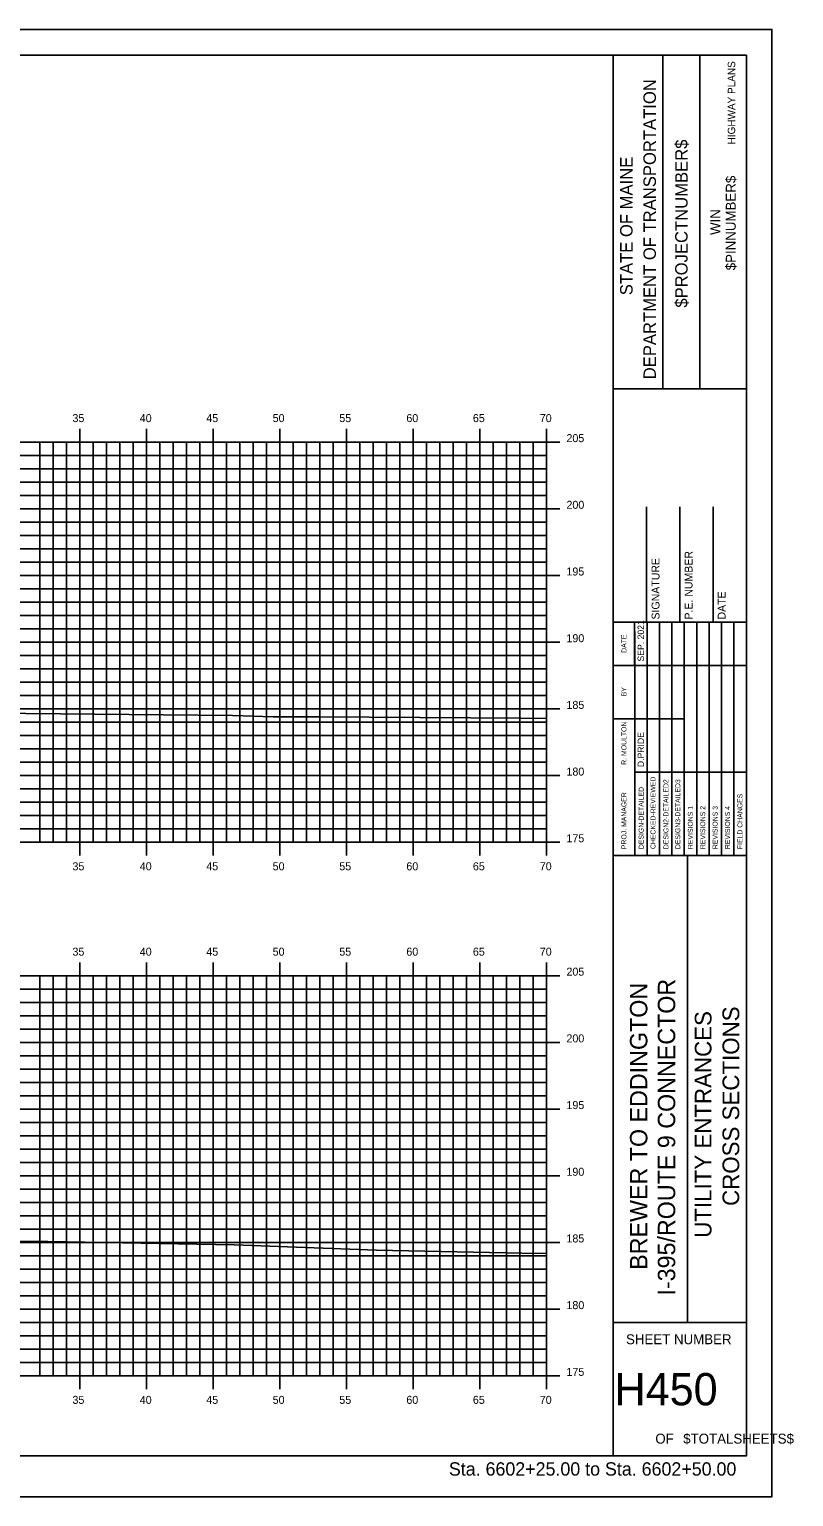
# Model space of a CAD drawing. Extents: x 1724183 to 1724355, y 459560 to 459670.
# Drawn here: x 1724297.4 to 1724354.8, y 459559.6 to 459669.6 of the extents above; entities that cross this region are included whole.
import ezdxf

# ---------------------------------------------------------------- set-up
doc = ezdxf.new("R2010")
doc.units = 0
for name, color, linetype in [('BORDER', 7, 'Continuous'), ('H_V ANNOTATION', 7, 'Continuous'), ('HIGHWAY_TITLE', 7, 'Continuous'), ('MAJOR', 7, 'Continuous'), ('MINOR', 7, 'Continuous'), ('PLOT BOUNDARY', 7, 'Continuous'), ('S_Roadway_Centerline', 7, 'Continuous')]:
    doc.layers.add(name, color=color, linetype=linetype)

msp = doc.modelspace()

# ---------------------------------------------------------------- linework, layer by layer
at = {"layer": 'BORDER'}
for p, q in [((1724341.23, 459562.61), (1724341.23, 459667.61)), ((1724344.96, 459642.61), (1724344.96, 459667.61)), ((1724347.75, 459642.61), (1724347.75, 459667.61)), ((1724341.23, 459642.61), (1724351.23, 459642.61)), ((1724343.73, 459625.12), (1724343.73, 459633.76)), ((1724346.23, 459625.12), (1724346.23, 459633.76)), ((1724348.73, 459625.12), (1724348.73, 459633.76)), ((1724341.23, 459625.12), (1724351.23, 459625.12)), ((1724341.23, 459607.62), (1724351.23, 459607.62)), ((1724346.82, 459572.62), (1724346.82, 459607.62)), ((1724341.23, 459572.62), (1724351.23, 459572.62))]:
    msp.add_line(p, q, dxfattribs=at)
msp.add_lwpolyline([(1724191.23, 459562.61), (1724351.23, 459562.61), (1724351.23, 459667.61), (1724191.23, 459667.61)], close=True, dxfattribs=at)
for points in [[(1724342.84, 459621.87), (1724342.84, 459625.12)], [(1724343.78, 459607.62), (1724343.78, 459625.12)], [(1724344.71, 459625.12), (1724344.71, 459607.62)], [(1724345.64, 459607.62), (1724345.64, 459625.12)], [(1724346.57, 459607.62), (1724346.57, 459625.12)], [(1724347.5, 459607.62), (1724347.5, 459625.12)], [(1724348.44, 459607.62), (1724348.44, 459625.12)], [(1724349.37, 459607.62), (1724349.37, 459625.12)], [(1724350.3, 459607.62), (1724350.3, 459625.12)], [(1724342.85, 459607.62), (1724342.85, 459624.41)], [(1724341.23, 459621.87), (1724351.23, 459621.87)], [(1724341.23, 459617.87), (1724342.85, 459617.87)], [(1724342.84, 459617.87), (1724346.57, 459617.87)], [(1724342.84, 459613.87), (1724351.23, 459613.87)]]:
    msp.add_lwpolyline(points, dxfattribs=at)
at = {"layer": 'MAJOR'}
for p, q in [((1724301.23, 459639.61), (1724301.23, 459638.61)), ((1724306.23, 459639.61), (1724306.23, 459638.61)), ((1724311.23, 459639.61), (1724311.23, 459638.61)), ((1724316.23, 459639.61), (1724316.23, 459638.61)), ((1724321.23, 459639.61), (1724321.23, 459638.61)), ((1724326.23, 459639.61), (1724326.23, 459638.61)), ((1724331.23, 459639.61), (1724331.23, 459638.61)), ((1724336.23, 459639.61), (1724336.23, 459638.61)), ((1724196.23, 459638.61), (1724336.23, 459638.61)), ((1724196.23, 459638.61), (1724336.23, 459638.61)), ((1724301.23, 459608.61), (1724301.23, 459638.61)), ((1724306.23, 459608.61), (1724306.23, 459638.61)), ((1724311.23, 459608.61), (1724311.23, 459638.61)), ((1724316.23, 459608.61), (1724316.23, 459638.61)), ((1724321.23, 459608.61), (1724321.23, 459638.61)), ((1724326.23, 459608.61), (1724326.23, 459638.61)), ((1724331.23, 459608.61), (1724331.23, 459638.61)), ((1724337.23, 459638.61), (1724335.23, 459638.61)), ((1724336.23, 459608.61), (1724336.23, 459638.61)), ((1724336.23, 459608.61), (1724336.23, 459638.61)), ((1724196.23, 459633.61), (1724336.23, 459633.61)), ((1724337.23, 459633.61), (1724335.23, 459633.61)), ((1724196.23, 459628.61), (1724336.23, 459628.61)), ((1724337.23, 459628.61), (1724335.23, 459628.61)), ((1724196.23, 459623.61), (1724336.23, 459623.61)), ((1724337.23, 459623.61), (1724335.23, 459623.61)), ((1724196.23, 459618.61), (1724336.23, 459618.61)), ((1724337.23, 459618.61), (1724335.23, 459618.61)), ((1724196.23, 459613.61), (1724336.23, 459613.61)), ((1724337.23, 459613.61), (1724335.23, 459613.61)), ((1724196.23, 459608.61), (1724336.23, 459608.61)), ((1724196.23, 459608.61), (1724336.23, 459608.61)), ((1724301.23, 459607.61), (1724301.23, 459608.61)), ((1724306.23, 459607.61), (1724306.23, 459608.61)), ((1724311.23, 459607.61), (1724311.23, 459608.61)), ((1724316.23, 459607.61), (1724316.23, 459608.61)), ((1724321.23, 459607.61), (1724321.23, 459608.61)), ((1724326.23, 459607.61), (1724326.23, 459608.61)), ((1724331.23, 459607.61), (1724331.23, 459608.61)), ((1724337.23, 459608.61), (1724335.23, 459608.61)), ((1724336.23, 459607.61), (1724336.23, 459608.61)), ((1724301.23, 459599.61), (1724301.23, 459598.61)), ((1724306.23, 459599.61), (1724306.23, 459598.61)), ((1724311.23, 459599.61), (1724311.23, 459598.61)), ((1724316.23, 459599.61), (1724316.23, 459598.61)), ((1724321.23, 459599.61), (1724321.23, 459598.61)), ((1724326.23, 459599.61), (1724326.23, 459598.61)), ((1724331.23, 459599.61), (1724331.23, 459598.61)), ((1724336.23, 459599.61), (1724336.23, 459598.61)), ((1724196.23, 459598.61), (1724336.23, 459598.61)), ((1724196.23, 459598.61), (1724336.23, 459598.61)), ((1724301.23, 459568.61), (1724301.23, 459598.61)), ((1724306.23, 459568.61), (1724306.23, 459598.61)), ((1724311.23, 459568.61), (1724311.23, 459598.61)), ((1724316.23, 459568.61), (1724316.23, 459598.61)), ((1724321.23, 459568.61), (1724321.23, 459598.61)), ((1724326.23, 459568.61), (1724326.23, 459598.61)), ((1724331.23, 459568.61), (1724331.23, 459598.61)), ((1724337.23, 459598.61), (1724335.23, 459598.61)), ((1724336.23, 459568.61), (1724336.23, 459598.61)), ((1724336.23, 459568.61), (1724336.23, 459598.61)), ((1724196.23, 459593.61), (1724336.23, 459593.61)), ((1724337.23, 459593.61), (1724335.23, 459593.61)), ((1724196.23, 459588.61), (1724336.23, 459588.61)), ((1724337.23, 459588.61), (1724335.23, 459588.61)), ((1724196.23, 459583.61), (1724336.23, 459583.61)), ((1724337.23, 459583.61), (1724335.23, 459583.61)), ((1724196.23, 459578.61), (1724336.23, 459578.61)), ((1724337.23, 459578.61), (1724335.23, 459578.61)), ((1724196.23, 459573.61), (1724336.23, 459573.61)), ((1724337.23, 459573.61), (1724335.23, 459573.61)), ((1724196.23, 459568.61), (1724336.23, 459568.61)), ((1724196.23, 459568.61), (1724336.23, 459568.61)), ((1724301.23, 459567.61), (1724301.23, 459568.61)), ((1724306.23, 459567.61), (1724306.23, 459568.61)), ((1724311.23, 459567.61), (1724311.23, 459568.61)), ((1724316.23, 459567.61), (1724316.23, 459568.61)), ((1724321.23, 459567.61), (1724321.23, 459568.61)), ((1724326.23, 459567.61), (1724326.23, 459568.61)), ((1724331.23, 459567.61), (1724331.23, 459568.61)), ((1724337.23, 459568.61), (1724335.23, 459568.61)), ((1724336.23, 459567.61), (1724336.23, 459568.61))]:
    msp.add_line(p, q, dxfattribs=at)
at = {"layer": 'MINOR'}
for p, q in [((1724298.23, 459608.61), (1724298.23, 459638.61)), ((1724299.23, 459608.61), (1724299.23, 459638.61)), ((1724300.23, 459608.61), (1724300.23, 459638.61)), ((1724302.23, 459608.61), (1724302.23, 459638.61)), ((1724303.23, 459608.61), (1724303.23, 459638.61)), ((1724304.23, 459608.61), (1724304.23, 459638.61)), ((1724305.23, 459608.61), (1724305.23, 459638.61)), ((1724307.23, 459608.61), (1724307.23, 459638.61)), ((1724308.23, 459608.61), (1724308.23, 459638.61)), ((1724309.23, 459608.61), (1724309.23, 459638.61)), ((1724310.23, 459608.61), (1724310.23, 459638.61)), ((1724312.23, 459608.61), (1724312.23, 459638.61)), ((1724313.23, 459608.61), (1724313.23, 459638.61)), ((1724314.23, 459608.61), (1724314.23, 459638.61)), ((1724315.23, 459608.61), (1724315.23, 459638.61)), ((1724317.23, 459608.61), (1724317.23, 459638.61)), ((1724318.23, 459608.61), (1724318.23, 459638.61)), ((1724319.23, 459608.61), (1724319.23, 459638.61)), ((1724320.23, 459608.61), (1724320.23, 459638.61)), ((1724322.23, 459608.61), (1724322.23, 459638.61)), ((1724323.23, 459608.61), (1724323.23, 459638.61)), ((1724324.23, 459608.61), (1724324.23, 459638.61)), ((1724325.23, 459608.61), (1724325.23, 459638.61)), ((1724327.23, 459608.61), (1724327.23, 459638.61)), ((1724328.23, 459608.61), (1724328.23, 459638.61)), ((1724329.23, 459608.61), (1724329.23, 459638.61)), ((1724330.23, 459608.61), (1724330.23, 459638.61)), ((1724332.23, 459608.61), (1724332.23, 459638.61)), ((1724333.23, 459608.61), (1724333.23, 459638.61)), ((1724334.23, 459608.61), (1724334.23, 459638.61)), ((1724335.23, 459608.61), (1724335.23, 459638.61)), ((1724196.23, 459637.61), (1724336.23, 459637.61)), ((1724336.23, 459637.61), (1724335.23, 459637.61)), ((1724196.23, 459636.61), (1724336.23, 459636.61)), ((1724336.23, 459636.61), (1724335.23, 459636.61)), ((1724196.23, 459635.61), (1724336.23, 459635.61)), ((1724336.23, 459635.61), (1724335.23, 459635.61)), ((1724196.23, 459634.61), (1724336.23, 459634.61)), ((1724336.23, 459634.61), (1724335.23, 459634.61)), ((1724196.23, 459632.61), (1724336.23, 459632.61)), ((1724336.23, 459632.61), (1724335.23, 459632.61)), ((1724196.23, 459631.61), (1724336.23, 459631.61)), ((1724196.23, 459630.61), (1724336.23, 459630.61)), ((1724336.23, 459631.61), (1724335.23, 459631.61)), ((1724336.23, 459630.61), (1724335.23, 459630.61)), ((1724196.23, 459629.61), (1724336.23, 459629.61)), ((1724336.23, 459629.61), (1724335.23, 459629.61)), ((1724196.23, 459627.61), (1724336.23, 459627.61)), ((1724336.23, 459627.61), (1724335.23, 459627.61)), ((1724196.23, 459626.61), (1724336.23, 459626.61)), ((1724336.23, 459626.61), (1724335.23, 459626.61)), ((1724196.23, 459625.61), (1724336.23, 459625.61)), ((1724336.23, 459625.61), (1724335.23, 459625.61)), ((1724196.23, 459624.61), (1724336.23, 459624.61)), ((1724336.23, 459624.61), (1724335.23, 459624.61)), ((1724196.23, 459622.61), (1724336.23, 459622.61)), ((1724336.23, 459622.61), (1724335.23, 459622.61)), ((1724196.23, 459621.61), (1724336.23, 459621.61)), ((1724336.23, 459621.61), (1724335.23, 459621.61)), ((1724196.23, 459620.61), (1724336.23, 459620.61)), ((1724196.23, 459619.61), (1724336.23, 459619.61)), ((1724336.23, 459620.61), (1724335.23, 459620.61)), ((1724336.23, 459619.61), (1724335.23, 459619.61)), ((1724196.23, 459617.61), (1724336.23, 459617.61)), ((1724336.23, 459617.61), (1724335.23, 459617.61)), ((1724196.23, 459616.61), (1724336.23, 459616.61)), ((1724336.23, 459616.61), (1724335.23, 459616.61)), ((1724196.23, 459615.61), (1724336.23, 459615.61)), ((1724336.23, 459615.61), (1724335.23, 459615.61)), ((1724196.23, 459614.61), (1724336.23, 459614.61)), ((1724336.23, 459614.61), (1724335.23, 459614.61)), ((1724196.23, 459612.61), (1724336.23, 459612.61)), ((1724336.23, 459612.61), (1724335.23, 459612.61)), ((1724196.23, 459611.61), (1724336.23, 459611.61)), ((1724336.23, 459611.61), (1724335.23, 459611.61)), ((1724196.23, 459610.61), (1724336.23, 459610.61)), ((1724336.23, 459610.61), (1724335.23, 459610.61)), ((1724196.23, 459609.61), (1724336.23, 459609.61)), ((1724336.23, 459609.61), (1724335.23, 459609.61)), ((1724196.23, 459597.61), (1724336.23, 459597.61)), ((1724298.23, 459568.61), (1724298.23, 459598.61)), ((1724299.23, 459568.61), (1724299.23, 459598.61)), ((1724300.23, 459568.61), (1724300.23, 459598.61)), ((1724302.23, 459568.61), (1724302.23, 459598.61)), ((1724303.23, 459568.61), (1724303.23, 459598.61)), ((1724304.23, 459568.61), (1724304.23, 459598.61)), ((1724305.23, 459568.61), (1724305.23, 459598.61)), ((1724307.23, 459568.61), (1724307.23, 459598.61)), ((1724308.23, 459568.61), (1724308.23, 459598.61)), ((1724309.23, 459568.61), (1724309.23, 459598.61)), ((1724310.23, 459568.61), (1724310.23, 459598.61)), ((1724312.23, 459568.61), (1724312.23, 459598.61)), ((1724313.23, 459568.61), (1724313.23, 459598.61)), ((1724314.23, 459568.61), (1724314.23, 459598.61)), ((1724315.23, 459568.61), (1724315.23, 459598.61)), ((1724317.23, 459568.61), (1724317.23, 459598.61)), ((1724318.23, 459568.61), (1724318.23, 459598.61)), ((1724319.23, 459568.61), (1724319.23, 459598.61)), ((1724320.23, 459568.61), (1724320.23, 459598.61)), ((1724322.23, 459568.61), (1724322.23, 459598.61)), ((1724323.23, 459568.61), (1724323.23, 459598.61)), ((1724324.23, 459568.61), (1724324.23, 459598.61)), ((1724325.23, 459568.61), (1724325.23, 459598.61)), ((1724327.23, 459568.61), (1724327.23, 459598.61)), ((1724328.23, 459568.61), (1724328.23, 459598.61)), ((1724329.23, 459568.61), (1724329.23, 459598.61)), ((1724330.23, 459568.61), (1724330.23, 459598.61)), ((1724332.23, 459568.61), (1724332.23, 459598.61)), ((1724333.23, 459568.61), (1724333.23, 459598.61)), ((1724334.23, 459568.61), (1724334.23, 459598.61)), ((1724335.23, 459568.61), (1724335.23, 459598.61)), ((1724336.23, 459597.61), (1724335.23, 459597.61)), ((1724196.23, 459596.61), (1724336.23, 459596.61)), ((1724336.23, 459596.61), (1724335.23, 459596.61)), ((1724196.23, 459595.61), (1724336.23, 459595.61)), ((1724336.23, 459595.61), (1724335.23, 459595.61)), ((1724196.23, 459594.61), (1724336.23, 459594.61)), ((1724336.23, 459594.61), (1724335.23, 459594.61)), ((1724196.23, 459592.61), (1724336.23, 459592.61)), ((1724336.23, 459592.61), (1724335.23, 459592.61)), ((1724196.23, 459591.61), (1724336.23, 459591.61)), ((1724336.23, 459591.61), (1724335.23, 459591.61)), ((1724196.23, 459590.61), (1724336.23, 459590.61)), ((1724336.23, 459590.61), (1724335.23, 459590.61)), ((1724196.23, 459589.61), (1724336.23, 459589.61)), ((1724336.23, 459589.61), (1724335.23, 459589.61)), ((1724196.23, 459587.61), (1724336.23, 459587.61)), ((1724196.23, 459586.61), (1724336.23, 459586.61)), ((1724336.23, 459587.61), (1724335.23, 459587.61)), ((1724336.23, 459586.61), (1724335.23, 459586.61)), ((1724196.23, 459585.61), (1724336.23, 459585.61)), ((1724336.23, 459585.61), (1724335.23, 459585.61)), ((1724196.23, 459584.61), (1724336.23, 459584.61)), ((1724336.23, 459584.61), (1724335.23, 459584.61)), ((1724196.23, 459582.61), (1724336.23, 459582.61)), ((1724336.23, 459582.61), (1724335.23, 459582.61)), ((1724196.23, 459581.61), (1724336.23, 459581.61)), ((1724336.23, 459581.61), (1724335.23, 459581.61)), ((1724196.23, 459580.61), (1724336.23, 459580.61)), ((1724336.23, 459580.61), (1724335.23, 459580.61)), ((1724196.23, 459579.61), (1724336.23, 459579.61)), ((1724336.23, 459579.61), (1724335.23, 459579.61)), ((1724196.23, 459577.61), (1724336.23, 459577.61)), ((1724336.23, 459577.61), (1724335.23, 459577.61)), ((1724196.23, 459576.61), (1724336.23, 459576.61)), ((1724196.23, 459575.61), (1724336.23, 459575.61)), ((1724336.23, 459576.61), (1724335.23, 459576.61)), ((1724336.23, 459575.61), (1724335.23, 459575.61)), ((1724196.23, 459574.61), (1724336.23, 459574.61)), ((1724336.23, 459574.61), (1724335.23, 459574.61)), ((1724196.23, 459572.61), (1724336.23, 459572.61)), ((1724336.23, 459572.61), (1724335.23, 459572.61)), ((1724196.23, 459571.61), (1724336.23, 459571.61)), ((1724336.23, 459571.61), (1724335.23, 459571.61)), ((1724196.23, 459570.61), (1724336.23, 459570.61)), ((1724336.23, 459570.61), (1724335.23, 459570.61)), ((1724196.23, 459569.61), (1724336.23, 459569.61)), ((1724336.23, 459569.61), (1724335.23, 459569.61))]:
    msp.add_line(p, q, dxfattribs=at)
at = {"layer": 'PLOT BOUNDARY'}
msp.add_lwpolyline([(1724183.14, 459559.55), (1724353.14, 459559.55), (1724353.14, 459669.55), (1724183.14, 459669.55)], close=True, dxfattribs=at)
at = {"layer": 'S_Roadway_Centerline'}
for points in [[(1724196.23, 459621.01), (1724202.87, 459620.97), (1724210.73, 459620.93), (1724221.32, 459620.44), (1724223.87, 459620.3), (1724226.15, 459620.21), (1724235.09, 459620), (1724244.6, 459619.56), (1724248.06, 459619.5), (1724258.68, 459619.37), (1724270.2, 459618.67), (1724270.63, 459618.66), (1724271.14, 459618.64), (1724291.82, 459618.31), (1724294.57, 459618.28), (1724312.67, 459618.11), (1724315.73, 459618.02), (1724319.16, 459618.01), (1724334.32, 459617.92), (1724336.23, 459617.88)], [(1724196.23, 459582.21), (1724199.86, 459582.21), (1724204.03, 459581.98), (1724224.07, 459580.72), (1724224.93, 459580.68), (1724225.67, 459580.68), (1724240.81, 459580.73), (1724247.35, 459580.74), (1724247.69, 459580.74), (1724248.09, 459580.7), (1724259.98, 459579.47), (1724268.97, 459579.48), (1724274.27, 459579.41), (1724283.45, 459579.01), (1724291.81, 459578.76), (1724298.81, 459578.69), (1724312.8, 459578.43), (1724323.48, 459578.03), (1724334.38, 459577.81), (1724336.23, 459577.79)]]:
    msp.add_lwpolyline(points, dxfattribs=at)

# ---------------------------------------------------------------- texts
at = {"layer": 'BORDER'}
for s, height, p in [('DEPARTMENT OF TRANSPORTATION', 0.9318, (1724344.44, 459643.32)), ('$PROJECTNUMBER$', 0.9318, (1724346.82, 459648.69)), ('STATE OF MAINE', 0.9318, (1724342.69, 459649.62)), ('$PINNUMBER$', 0.7453, (1724350.43, 459651.49)), ('WIN', 0.745, (1724349.27, 459654.14)), ('SIGNATURE', 0.591, (1724344.71, 459625.31)), ('P.E. NUMBER', 0.5906, (1724347.19, 459625.31)), ('DATE', 0.591, (1724349.67, 459625.31)), ('SEP. 2021', 0.485, (1724343.55, 459622.16)), ('DATE', 0.371, (1724342.23, 459622.82)), ('BY', 0.371, (1724342.23, 459619.55)), ('R. MOULTON', 0.373, (1724342.23, 459614.42)), ('D.PRIDE', 0.485, (1724343.55, 459614.24)), ('CHECKED-REVIEWED', 0.3727, (1724344.41, 459608.1)), ('DESIGN2-DETAILED2', 0.3727, (1724345.38, 459608.1)), ('DESIGN3-DETAILED3', 0.3727, (1724346.27, 459608.1)), ('PROJ. MANAGER', 0.3727, (1724342.23, 459608.1)), ('DESIGN-DETAILED', 0.3727, (1724343.52, 459608.1)), ('FIELD CHANGES', 0.3727, (1724350.93, 459608.1)), ('REVISIONS 1', 0.3727, (1724347.21, 459608.1)), ('REVISIONS 2', 0.3727, (1724348.14, 459608.1)), ('REVISIONS 3', 0.3727, (1724349.07, 459608.1)), ('REVISIONS 4', 0.3727, (1724350, 459608.1)), ('UTILITY ENTRANCES', 1.25, (1724348.61, 459578.96)), ('CROSS SECTIONS', 1.25, (1724350.69, 459581.35))]:
    msp.add_text(s, height=height, rotation=90, dxfattribs=at).set_placement(p)
for s, height, p in [('SHEET NUMBER', 0.7453, (1724342.2, 459570.98)), ('H450', 2.419, (1724341.34, 459566.4)), ('OF', 0.745, (1724344.4, 459563.53)), ('$TOTALSHEETS$', 0.7453, (1724346.49, 459563.53))]:
    msp.add_text(s, height=height, dxfattribs=at).set_placement(p)
at = {"layer": 'H_V ANNOTATION'}
for s, height, p in [('35', 0.6, (1724300.67, 459640.11)), ('40', 0.6, (1724305.72, 459640.11)), ('45', 0.6, (1724310.71, 459640.11)), ('50', 0.6, (1724315.69, 459640.11)), ('55', 0.6, (1724320.69, 459640.11)), ('60', 0.6, (1724325.72, 459640.11)), ('65', 0.6, (1724330.71, 459640.11)), ('70', 0.6, (1724335.73, 459640.11)), ('205', 0.6, (1724337.73, 459638.61)), ('200', 0.6, (1724337.73, 459633.61)), ('195', 0.6, (1724337.73, 459628.61)), ('190', 0.6, (1724337.73, 459623.61)), ('185', 0.6, (1724337.73, 459618.61)), ('180', 0.6, (1724337.73, 459613.61)), ('175', 0.6, (1724337.73, 459608.61)), ('35', 0.6, (1724300.67, 459606.51)), ('40', 0.6, (1724305.72, 459606.51)), ('45', 0.6, (1724310.71, 459606.51)), ('50', 0.6, (1724315.69, 459606.51)), ('55', 0.6, (1724320.69, 459606.51)), ('60', 0.6, (1724325.72, 459606.51)), ('65', 0.6, (1724330.71, 459606.51)), ('70', 0.6, (1724335.73, 459606.51)), ('35', 0.6, (1724300.67, 459600.11)), ('40', 0.6, (1724305.72, 459600.11)), ('45', 0.6, (1724310.71, 459600.11)), ('50', 0.6, (1724315.69, 459600.11)), ('55', 0.6, (1724320.69, 459600.11)), ('60', 0.6, (1724325.72, 459600.11)), ('65', 0.6, (1724330.71, 459600.11)), ('70', 0.6, (1724335.73, 459600.11)), ('205', 0.6, (1724337.73, 459598.61)), ('200', 0.6, (1724337.73, 459593.61)), ('195', 0.6, (1724337.73, 459588.61)), ('190', 0.6, (1724337.73, 459583.61)), ('185', 0.6, (1724337.73, 459578.61)), ('180', 0.6, (1724337.73, 459573.61)), ('175', 0.6, (1724337.73, 459568.61)), ('35', 0.6, (1724300.67, 459566.51)), ('40', 0.6, (1724305.72, 459566.51)), ('45', 0.6, (1724310.71, 459566.51)), ('50', 0.6, (1724315.69, 459566.51)), ('55', 0.6, (1724320.69, 459566.51)), ('60', 0.6, (1724325.72, 459566.51)), ('65', 0.6, (1724330.71, 459566.51)), ('70', 0.6, (1724335.73, 459566.51)), ('Sta. 6602+25.00 to Sta. 6602+50.00', 1.0002, (1724328.91, 459561.13))]:
    msp.add_text(s, height=height, dxfattribs=at).set_placement(p)
at = {"layer": 'HIGHWAY_TITLE'}
for s, height, p in [('HIGHWAY PLANS', 0.559, (1724350.39, 459660.93)), ('BREWER TO EDDINGTON', 1.3043, (1724343.8, 459576.56)), ('I-395/ROUTE 9 CONNECTOR', 1.3043, (1724345.89, 459574.63))]:
    msp.add_text(s, height=height, rotation=90, dxfattribs=at).set_placement(p)

doc.saveas('drawing.dxf')
